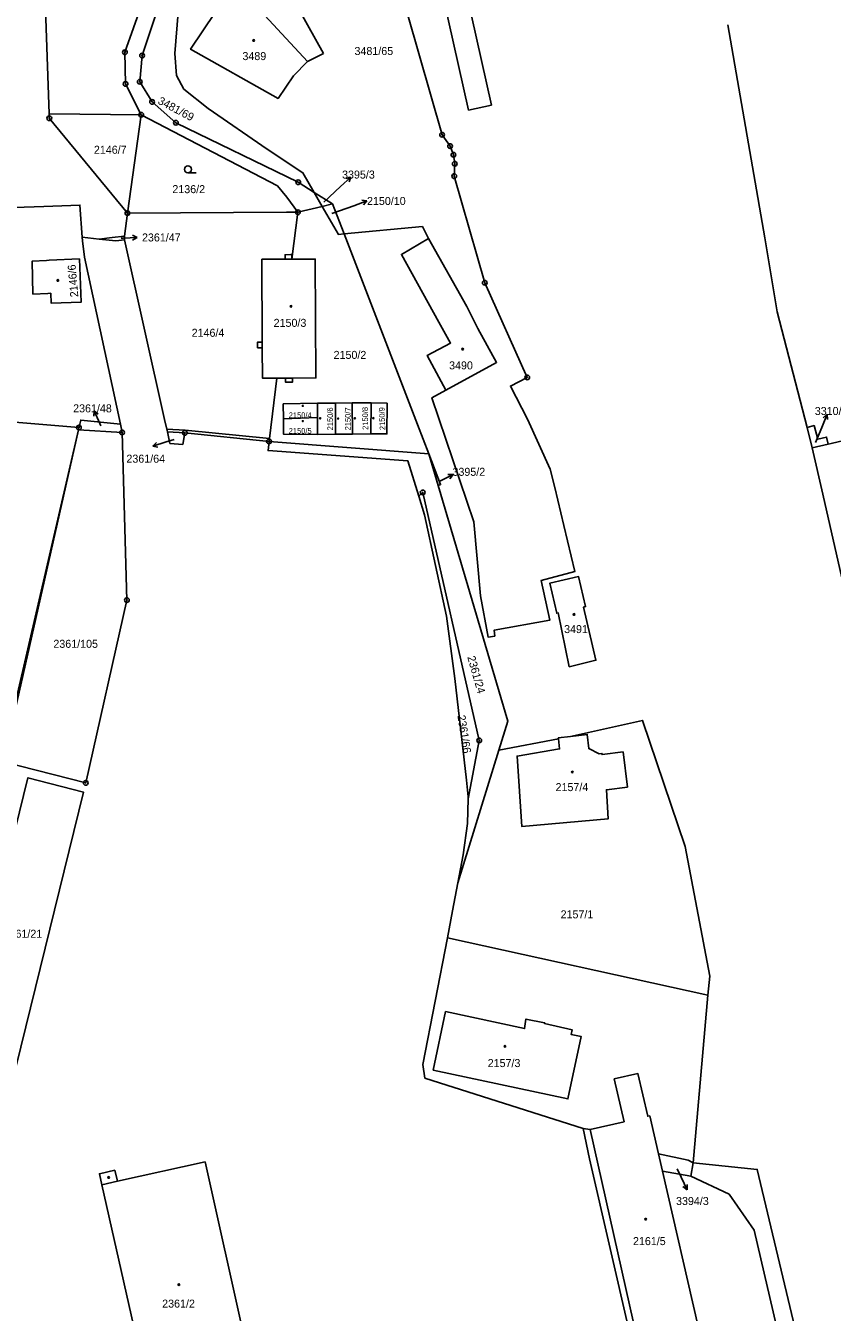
# Model space of a CAD drawing. Extents: x -733394 to -722299, y -1082822 to -1075049.
# Drawn here: x -728982 to -728810.6, y -1079569.2 to -1079295.9 of the extents above; entities that cross this region are included whole.
import ezdxf

# ---------------------------------------------------------------- set-up
doc = ezdxf.new("R2010")
doc.units = 0
for name, color, linetype in [('Hranice parcel', 7, 'Continuous'), ('Parcelní čísla', 7, 'Continuous'), ('Pop  PČ popisy', 7, 'Continuous'), ('Vnitřní kresba', 7, 'Continuous'), ('Značky bodu BP', 7, 'Continuous'), ('Značky budov', 7, 'Continuous'), ('Značky kultur', 7, 'Continuous')]:
    doc.layers.add(name, color=color, linetype=linetype)

msp = doc.modelspace()

# ---------------------------------------------------------------- linework, layer by layer
at = {"layer": 'Hranice parcel'}
for p, q in [((-728977, -1079314.6), (-728957.44, -1079314.81)), ((-728957.44, -1079314.81), (-728960.38, -1079335.68)), ((-728918.97, -1079334.26), (-728920.68, -1079331.29)), ((-728920.68, -1079331.29), (-728916.8, -1079333.72)), ((-728916.8, -1079333.72), (-728918.97, -1079334.26)), ((-728916.8, -1079333.72), (-728914.34, -1079340.12)), ((-728960.96, -1079340.61), (-728960.38, -1079335.68)), ((-728925.45, -1079345.47), (-728924.14, -1079335.53)), ((-728918.97, -1079334.26), (-728924.14, -1079335.53)), ((-728970, -1079340.81), (-728966.36, -1079341.2)), ((-728960.96, -1079340.61), (-728961.03, -1079341.37)), ((-728919.98, -1079376.05), (-728916.17, -1079376.1)), ((-728919.97, -1079379.14), (-728919.98, -1079376.05)), ((-728916.17, -1079376.1), (-728912.62, -1079376.03)), ((-728916.14, -1079382.67), (-728916.17, -1079376.1)), ((-728912.62, -1079376.03), (-728908.61, -1079376.04)), ((-728912.58, -1079382.65), (-728912.62, -1079376.03)), ((-728908.63, -1079382.62), (-728908.61, -1079376.04)), ((-728927.24, -1079379.43), (-728919.97, -1079379.14)), ((-728919.99, -1079382.7), (-728919.97, -1079379.14)), ((-728970.76, -1079381.73), (-728992.47, -1079475.32)), ((-728970.67, -1079381.27), (-728970.76, -1079381.73)), ((-728970.76, -1079381.73), (-728961.51, -1079382.29)), ((-728961.83, -1079380.55), (-728961.51, -1079382.29)), ((-728951.88, -1079382.2), (-728948.16, -1079382.38)), ((-728948.16, -1079382.38), (-728930.29, -1079384.21)), ((-728916.14, -1079382.67), (-728919.99, -1079382.7)), ((-728912.58, -1079382.65), (-728916.14, -1079382.67)), ((-728908.63, -1079382.62), (-728912.58, -1079382.65)), ((-728814.87, -1079385.56), (-728815.98, -1079381.25)), ((-728930.29, -1079384.21), (-728896.34, -1079386.82)), ((-728811.48, -1079384.78), (-728814.87, -1079385.56)), ((-728894.34, -1079393.59), (-728896.34, -1079386.82)), ((-728868.79, -1079447.37), (-728881.47, -1079449.76)), ((-728881.47, -1079449.76), (-728890.18, -1079478)), ((-728863.54, -1079530.2), (-728862.04, -1079530.36)), ((-728846.7, -1079539.26), (-728847.54, -1079535.58)), ((-728840.68, -1079540.29), (-728840.19, -1079537.43)), ((-728840.68, -1079540.29), (-728846.7, -1079539.26))]:
    msp.add_line(p, q, dxfattribs=at)
for points in [[(-728912.74, -1079245.38), (-728910.54, -1079259.52), (-728893.52, -1079319.05), (-728891.82, -1079321.46), (-728891.1, -1079323.29), (-728890.81, -1079325.21), (-728890.92, -1079327.85), (-728884.46, -1079350.5), (-728875.41, -1079370.6), (-728879, -1079372.46), (-728875.4, -1079379.44), (-728870.58, -1079390.09), (-728869.56, -1079394), (-728867.67, -1079402.06), (-728865.28, -1079411.81), (-728872.48, -1079413.75), (-728870.6, -1079422.15), (-728882.42, -1079424.3), (-728882.34, -1079425.56), (-728883.75, -1079425.77), (-728885.37, -1079417.02), (-728886.78, -1079401.3), (-728895.68, -1079374.93), (-728892.72, -1079373.31)], [(-728887.92, -1079313.83), (-728902.94, -1079246.72), (-728898, -1079245.62), (-728883.04, -1079312.75), (-728887.92, -1079313.83)], [(-728944.91, -1079270.8), (-728945.85, -1079278.22), (-728947.41, -1079284.23), (-728949.61, -1079293.11), (-728950.27, -1079301.77), (-728949.94, -1079306.43), (-728948.4, -1079309.35), (-728943.21, -1079313.51), (-728930.69, -1079322.08), (-728923.08, -1079327.12), (-728920.68, -1079331.29)], [(-728972.25, -1079272.01), (-728975.83, -1079274.11), (-728977.55, -1079276.79), (-728978.15, -1079279.6), (-728977.9, -1079288.27), (-728977, -1079314.6)], [(-728957.44, -1079314.81), (-728960.78, -1079308.25), (-728960.91, -1079301.53), (-728953.23, -1079279.78), (-728952.6, -1079277.12), (-728955.49, -1079272.58)], [(-728920.68, -1079331.29), (-728924.09, -1079329.15), (-728950.08, -1079316.5), (-728955.12, -1079312.08), (-728957.76, -1079307.79), (-728957.27, -1079302.23), (-728947.05, -1079271.55)], [(-728918.73, -1079301.8), (-728928.91, -1079283.44), (-728936.67, -1079287.78), (-728941.71, -1079293.11), (-728946.96, -1079300.89), (-728928.38, -1079311.35), (-728925.08, -1079306.51), (-728922.11, -1079303.51), (-728918.73, -1079301.8)], [(-728832.77, -1079295.73), (-728824.94, -1079340.97), (-728822.31, -1079356.65), (-728815.98, -1079381.25)], [(-728960.38, -1079335.68), (-728976.97, -1079315.53), (-728977, -1079314.6)], [(-728924.14, -1079335.53), (-728926.53, -1079332.3), (-728928.51, -1079329.93), (-728957.44, -1079314.81)], [(-728990.3, -1079335.57), (-728984.4, -1079334.53), (-728978.1, -1079334.32), (-728976.22, -1079334.24), (-728970.48, -1079334), (-728970, -1079340.81)], [(-728960.38, -1079335.68), (-728926.58, -1079335.5), (-728924.14, -1079335.53)], [(-728914.34, -1079340.12), (-728915.53, -1079340.23), (-728918.97, -1079334.26)], [(-728896.39, -1079341.08), (-728897.68, -1079338.52), (-728914.34, -1079340.12)], [(-728961.83, -1079380.55), (-728969.46, -1079345.08), (-728969.94, -1079341.6), (-728970, -1079340.81)], [(-728966.36, -1079341.2), (-728963.61, -1079340.9), (-728960.96, -1079340.61)], [(-728961.03, -1079341.37), (-728962.87, -1079341.58), (-728966.36, -1079341.2)], [(-728961.03, -1079341.37), (-728952.49, -1079379.52), (-728952.02, -1079381.58), (-728951.88, -1079382.2)], [(-728896.34, -1079386.82), (-728898.75, -1079380.59), (-728914.34, -1079340.12)], [(-728896.39, -1079341.08), (-728902.17, -1079344.48), (-728894.18, -1079358.88), (-728891.72, -1079363.32), (-728896.72, -1079365.98), (-728892.72, -1079373.31)], [(-728892.72, -1079373.31), (-728881.94, -1079367.43), (-728885.95, -1079360.24), (-728888.25, -1079355.52), (-728896.39, -1079341.08)], [(-728928.61, -1079370.75), (-728931.68, -1079370.76), (-728931.71, -1079364.3), (-728932.71, -1079364.31), (-728932.72, -1079363.11), (-728931.72, -1079363.1), (-728931.8, -1079345.5), (-728926.88, -1079345.48), (-728926.88, -1079344.53), (-728925.67, -1079344.52), (-728925.46, -1079344.52), (-728925.45, -1079345.47)], [(-728970.56, -1079345.41), (-728970.23, -1079354.64), (-728976.57, -1079354.84), (-728976.67, -1079352.72), (-728977.27, -1079352.75), (-728980.47, -1079352.9), (-728980.58, -1079345.9), (-728977.6, -1079345.74), (-728977, -1079345.71), (-728970.56, -1079345.41)], [(-728925.45, -1079345.47), (-728920.45, -1079345.45), (-728920.33, -1079370.71), (-728925.31, -1079370.73), (-728925.31, -1079371.63), (-728926.77, -1079371.64), (-728926.78, -1079370.74), (-728928.61, -1079370.75)], [(-728930.29, -1079384.21), (-728930.21, -1079383.57), (-728928.61, -1079370.75)], [(-728927.24, -1079379.43), (-728927.26, -1079376.24), (-728919.98, -1079376.05)], [(-728908.61, -1079376.04), (-728905.21, -1079376.09), (-728905.25, -1079382.6), (-728908.63, -1079382.62)], [(-729016.72, -1079378.28), (-728993.71, -1079379.34), (-728970.67, -1079381.27)], [(-728970.67, -1079381.27), (-728970.49, -1079380.54), (-728970.29, -1079379.67), (-728961.83, -1079380.55)], [(-728919.99, -1079382.7), (-728927.21, -1079382.67), (-728927.24, -1079379.43)], [(-728986.73, -1079452.25), (-728986.57, -1079451.59), (-728970.76, -1079381.73)], [(-728961.51, -1079382.29), (-728960.47, -1079417.9), (-728969.24, -1079456.75), (-728986.73, -1079452.25)], [(-728948.16, -1079382.38), (-728948.63, -1079384.84), (-728951.33, -1079384.64), (-728951.88, -1079382.2)], [(-728815.98, -1079381.25), (-728814.47, -1079380.84), (-728813.7, -1079383.73), (-728811.82, -1079383.28), (-728811.48, -1079384.78)], [(-728811.48, -1079384.78), (-728810.87, -1079384.64), (-728806.7, -1079383.67), (-728802.64, -1079382.73), (-728796.56, -1079381.33), (-728794.43, -1079391.25), (-728794.08, -1079391.15), (-728791.96, -1079400.58), (-728792.3, -1079400.68), (-728786.5, -1079426.09), (-728786.16, -1079426), (-728784.04, -1079435.36), (-728784.77, -1079435.57), (-728783.29, -1079442.14), (-728782.22, -1079441.95), (-728780.82, -1079448.13), (-728782.06, -1079448.35), (-728779.11, -1079461.33), (-728777.84, -1079461.1), (-728776.45, -1079467.29)], [(-728898.48, -1079395.8), (-728900.8, -1079388.3), (-728930.49, -1079386.15), (-728930.29, -1079384.21)], [(-728814.87, -1079385.56), (-728812.63, -1079395.4), (-728795.36, -1079471.49), (-728794.16, -1079476.76), (-728790.7, -1079475.99), (-728791.89, -1079470.72), (-728779.32, -1079467.93)], [(-728894.34, -1079393.59), (-728893.82, -1079393.36), (-728896.34, -1079386.82)], [(-728881.47, -1079449.76), (-728879.57, -1079443.6), (-728894.34, -1079393.59)], [(-728898.48, -1079395.8), (-728897.64, -1079395.03), (-728885.62, -1079447.72), (-728887.96, -1079460.12)], [(-728887.96, -1079460.12), (-728887.95, -1079459.69), (-728888.36, -1079456.15), (-728890.84, -1079434.56), (-728892.6, -1079421.33), (-728897.26, -1079399.77), (-728898.48, -1079395.8)], [(-728866.51, -1079432.11), (-728860.85, -1079430.7), (-728863.46, -1079419.39), (-728863.03, -1079419.29), (-728864.5, -1079412.92), (-728870.64, -1079414.33), (-728869.16, -1079420.72), (-728868.83, -1079420.65), (-728866.51, -1079432.11)], [(-728840.19, -1079537.43), (-728837.02, -1079501.87), (-728836.66, -1079497.81), (-728841.88, -1079470.29), (-728850.91, -1079443.48), (-728866.25, -1079446.86)], [(-728866.25, -1079446.86), (-728862.69, -1079446.46), (-728862.35, -1079449.45), (-728860.14, -1079450.56), (-728859.56, -1079450.49), (-728859.53, -1079450.73), (-728855.07, -1079450.17), (-728854.15, -1079457.63), (-728858.61, -1079458.2), (-728858.22, -1079464.35), (-728876.55, -1079466.03), (-728877.58, -1079451.05), (-728868.55, -1079449.54), (-728868.79, -1079447.37)], [(-728866.25, -1079446.86), (-728868.82, -1079447.15), (-728868.79, -1079447.37)], [(-728995.89, -1079514.03), (-728981.51, -1079455.66), (-728969.72, -1079458.69), (-728984.04, -1079516.95), (-728995.89, -1079514.03)], [(-728890.18, -1079478), (-728889.07, -1079472.02), (-728888.1, -1079465.36), (-728887.96, -1079460.12)], [(-728890.18, -1079478), (-728891.28, -1079483.96), (-728892.38, -1079489.66), (-728897.59, -1079516.58), (-728897.18, -1079519.45), (-728863.54, -1079530.2)], [(-728895.43, -1079517.77), (-728892.77, -1079505.34), (-728875.98, -1079508.93), (-728875.72, -1079506.91), (-728871.73, -1079507.7), (-728871.76, -1079507.84), (-728865.9, -1079509.2), (-728866.11, -1079510.18), (-728863.96, -1079510.64), (-728866.8, -1079523.9), (-728895.43, -1079517.77)], [(-728862.04, -1079530.36), (-728854.84, -1079528.72), (-728856.93, -1079519.65), (-728851.9, -1079518.5), (-728849.82, -1079527.57), (-728849.4, -1079527.5), (-728847.54, -1079535.58)], [(-728863.54, -1079530.2), (-728862.22, -1079536.59), (-728841.12, -1079628.21), (-728846.24, -1079633.38), (-728836.69, -1079645.03), (-728833, -1079649.92), (-728823.45, -1079664.99), (-728819.2, -1079672.33), (-728812.42, -1079685.78), (-728808.98, -1079694.3), (-728806.12, -1079703.01), (-728804.65, -1079709.84)], [(-728846.7, -1079539.26), (-728839.13, -1079572.24), (-728839.43, -1079572.32), (-728838.06, -1079578.27), (-728844.2, -1079579.68), (-728845.57, -1079573.73), (-728852.01, -1079575.21), (-728862.04, -1079530.36)], [(-728847.54, -1079535.58), (-728841.26, -1079536.93), (-728840.19, -1079537.43)], [(-728963.02, -1079539.03), (-728962.49, -1079541.37), (-728943.88, -1079537.26), (-728935.41, -1079575.11), (-728933.96, -1079581.59), (-728937.23, -1079582.33), (-728934.29, -1079595.52), (-728941.68, -1079597.14), (-728952.86, -1079599.6), (-728965.81, -1079542.12), (-728966.34, -1079539.78), (-728963.02, -1079539.03)], [(-728765.26, -1079862.11), (-728759.56, -1079840.56), (-728766.76, -1079801.15), (-728771.96, -1079774.91), (-728779.79, -1079732.53), (-728804.18, -1079632.51), (-728814.51, -1079589.39), (-728826.55, -1079538.86), (-728840.19, -1079537.43)], [(-728780.22, -1079748.14), (-728787.28, -1079718.64), (-728796.46, -1079677.89), (-728805.52, -1079640.88), (-728812.26, -1079616.01), (-728827.18, -1079551.78), (-728832.53, -1079544.09), (-728840.68, -1079540.29)]]:
    msp.add_lwpolyline(points, dxfattribs=at)
at = {"layer": 'Pop  PČ popisy'}
for p, q in [((-728915.09, -1079330.08), (-728912.9, -1079328.03)), ((-728912.9, -1079328.03), (-728913.97, -1079328.35)), ((-728912.9, -1079328.03), (-728913.29, -1079329.08)), ((-728918.62, -1079333.4), (-728915.09, -1079330.08)), ((-728912.3, -1079334.13), (-728909.48, -1079333.1)), ((-728909.48, -1079333.1), (-728910.59, -1079332.98)), ((-728909.48, -1079333.1), (-728910.25, -1079333.92)), ((-728916.97, -1079335.8), (-728912.3, -1079334.13)), ((-728961.7, -1079341.04), (-728961.28, -1079341.02)), ((-728961.28, -1079341.02), (-728958.28, -1079340.86)), ((-728958.28, -1079340.86), (-728959.31, -1079340.42)), ((-728958.28, -1079340.86), (-728959.26, -1079341.42)), ((-728967.47, -1079377.69), (-728967.52, -1079378.81)), ((-728966.25, -1079380.43), (-728967.47, -1079377.69)), ((-728967.47, -1079377.69), (-728966.61, -1079378.4)), ((-728966.03, -1079380.92), (-728966.25, -1079380.43)), ((-728812.81, -1079381.21), (-728811.69, -1079378.43)), ((-728811.69, -1079378.43), (-728812.53, -1079379.17)), ((-728811.69, -1079378.43), (-728811.6, -1079379.54)), ((-728814.15, -1079384.45), (-728812.81, -1079381.21)), ((-728952.14, -1079384.3), (-728954.99, -1079385.23)), ((-728954.99, -1079385.23), (-728954.2, -1079384.44)), ((-728954.99, -1079385.23), (-728953.89, -1079385.39)), ((-728950.43, -1079383.76), (-728952.14, -1079384.3)), ((-728893.86, -1079392.61), (-728891.19, -1079391.25)), ((-728891.19, -1079391.25), (-728892.31, -1079391.26)), ((-728891.19, -1079391.25), (-728891.85, -1079392.15)), ((-728894.24, -1079392.81), (-728893.86, -1079392.61)), ((-728843.55, -1079538.77), (-728842.74, -1079540.5)), ((-728842.74, -1079540.5), (-728841.47, -1079543.22)), ((-728841.47, -1079543.22), (-728842.35, -1079542.52)), ((-728841.47, -1079543.22), (-728841.44, -1079542.1))]:
    msp.add_line(p, q, dxfattribs=at)
at = {"layer": 'Vnitřní kresba'}
for p, q in [((-728922.11, -1079303.51), (-728936.67, -1079287.78)), ((-728925.45, -1079345.47), (-728926.88, -1079345.48)), ((-728931.71, -1079364.3), (-728931.72, -1079363.1)), ((-728926.78, -1079370.74), (-728925.31, -1079370.73)), ((-728952.02, -1079381.58), (-728948.13, -1079381.8)), ((-728948.13, -1079381.8), (-728930.21, -1079383.57)), ((-728837.02, -1079501.87), (-728892.38, -1079489.66)), ((-728962.49, -1079541.37), (-728965.81, -1079542.12))]:
    msp.add_line(p, q, dxfattribs=at)
at = {"layer": 'Značky bodu BP'}
for centre, radius in [((-728960.91, -1079301.53), 0.5), ((-728960.91, -1079301.53), 0.0303), ((-728957.27, -1079302.23), 0.5), ((-728957.27, -1079302.23), 0.0303), ((-728960.78, -1079308.25), 0.5), ((-728960.78, -1079308.25), 0.0303), ((-728957.76, -1079307.79), 0.5), ((-728957.76, -1079307.79), 0.0303), ((-728955.12, -1079312.08), 0.5), ((-728955.12, -1079312.08), 0.0303), ((-728957.44, -1079314.81), 0.5), ((-728957.44, -1079314.81), 0.0303), ((-728976.97, -1079315.53), 0.5), ((-728976.97, -1079315.53), 0.0303), ((-728950.08, -1079316.5), 0.5), ((-728950.08, -1079316.5), 0.0303), ((-728893.52, -1079319.05), 0.5), ((-728893.52, -1079319.05), 0.0303), ((-728891.82, -1079321.46), 0.5), ((-728891.82, -1079321.46), 0.0303), ((-728891.1, -1079323.29), 0.5), ((-728890.81, -1079325.21), 0.5), ((-728891.1, -1079323.29), 0.0303), ((-728890.81, -1079325.21), 0.0303), ((-728890.92, -1079327.85), 0.5), ((-728890.92, -1079327.85), 0.0303), ((-728924.09, -1079329.15), 0.5), ((-728924.09, -1079329.15), 0.0303), ((-728960.38, -1079335.68), 0.5), ((-728960.38, -1079335.68), 0.0303), ((-728924.14, -1079335.53), 0.5), ((-728924.14, -1079335.53), 0.0303), ((-728884.46, -1079350.5), 0.5), ((-728884.46, -1079350.5), 0.0303), ((-728875.41, -1079370.6), 0.5), ((-728875.41, -1079370.6), 0.0303), ((-728970.67, -1079381.27), 0.5), ((-728970.67, -1079381.27), 0.0303), ((-728961.51, -1079382.29), 0.5), ((-728961.51, -1079382.29), 0.0303), ((-728948.16, -1079382.38), 0.5), ((-728948.16, -1079382.38), 0.0303), ((-728930.29, -1079384.21), 0.5), ((-728930.29, -1079384.21), 0.0303), ((-728897.64, -1079395.03), 0.5), ((-728897.64, -1079395.03), 0.0303), ((-728960.47, -1079417.9), 0.5), ((-728960.47, -1079417.9), 0.0303), ((-728885.62, -1079447.72), 0.5), ((-728885.62, -1079447.72), 0.0303), ((-728969.24, -1079456.75), 0.5), ((-728969.24, -1079456.75), 0.0303)]:
    msp.add_circle(centre, radius, dxfattribs=at)
at = {"layer": 'Značky budov'}
for centre, radius in [((-728933.56, -1079299.02), 0.175), ((-728975.16, -1079350.01), 0.175), ((-728925.62, -1079355.52), 0.175), ((-728889.13, -1079364.59), 0.175), ((-728923.11, -1079376.63), 0.122), ((-728923.12, -1079379.88), 0.122), ((-728919.41, -1079379.3), 0.122), ((-728915.61, -1079379.35), 0.122), ((-728912.05, -1079379.3), 0.122), ((-728908.14, -1079379.25), 0.122), ((-728865.5, -1079420.97), 0.175), ((-728865.86, -1079454.45), 0.175), ((-728880.14, -1079512.7), 0.175), ((-728964.35, -1079540.57), 0.175), ((-728850.26, -1079549.43), 0.175), ((-728949.44, -1079563.34), 0.175)]:
    msp.add_circle(centre, radius, dxfattribs=at)
at = {"layer": 'Značky kultur'}
msp.add_line((-728947.52, -1079327.15), (-728945.77, -1079327.15), dxfattribs=at)
msp.add_circle((-728947.52, -1079326.4), 0.75, dxfattribs=at)

# ---------------------------------------------------------------- texts
at = {"layer": 'Parcelní čísla'}
for s, height, p in [('3481/65', 1.7, (-728912.13, -1079302.11)), ('3489', 1.7, (-728935.94, -1079303.19)), ('2146/7', 1.7, (-728967.5, -1079323.09)), ('3395/3', 1.7, (-728914.77, -1079328.36)), ('2136/2', 1.7, (-728950.83, -1079331.46)), ('2150/10', 1.7, (-728909.47, -1079333.97)), ('2361/47', 1.7, (-728957.28, -1079341.72)), ('2150/3', 1.7, (-728929.31, -1079359.86)), ('2146/4', 1.7, (-728946.73, -1079361.97)), ('2150/2', 1.7, (-728916.57, -1079366.67)), ('3490', 1.7, (-728892.03, -1079368.9)), ('2361/48', 1.7, (-728971.91, -1079378.03)), ('3310/4', 1.7, (-728814.33, -1079378.59)), ('2150/4', 1.19, (-728926.1, -1079379.22)), ('2150/5', 1.19, (-728926.1, -1079382.55)), ('2361/64', 1.7, (-728960.59, -1079388.72)), ('3395/2', 1.7, (-728891.31, -1079391.51)), ('3491', 1.7, (-728867.59, -1079424.92)), ('2361/105', 1.7, (-728976.11, -1079428.05)), ('2157/4', 1.7, (-728869.41, -1079458.49)), ('2157/1', 1.7, (-728868.34, -1079485.52)), ('2361/21', 1.7, (-728986.69, -1079489.64)), ('2157/3', 1.7, (-728883.83, -1079517.12)), ('3394/3', 1.7, (-728843.81, -1079546.42)), ('2161/5', 1.7, (-728852.96, -1079554.94)), ('2361/2', 1.7, (-728952.99, -1079568.22))]:
    msp.add_text(s, height=height, dxfattribs=at).set_placement(p)
for s, height, rotation, p in [('3481/69', 1.7, 332, (-728954.06, -1079312.37)), ('2146/6', 1.7, 95, (-728970.8, -1079353.48)), ('2150/6', 1.19, 90, (-728916.71, -1079381.85)), ('2150/7', 1.19, 90, (-728912.94, -1079381.85)), ('2150/8', 1.19, 91, (-728909.21, -1079381.74)), ('2150/9', 1.19, 92, (-728905.58, -1079381.78)), ('2361/24', 1.7, 286, (-728888.18, -1079430.02)), ('2361/66', 1.7, 279, (-728890.27, -1079442.46))]:
    msp.add_text(s, height=height, rotation=rotation, dxfattribs=at).set_placement(p)

doc.saveas('drawing.dxf')
